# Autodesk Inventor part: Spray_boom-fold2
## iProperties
Created: 2007-04
Part Number: Spray_boom-fold2
Material: Steel, Mild
Document SubType Name: Sheet Metal
Designer: Admin
Density: 1 g/cm^3
Sheet Metal Rule: Default
Author: Admin
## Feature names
1. Bend5
2. Rectangular Pattern2
3. Plate1
4. Plate2
5. Bend1
6. Plate4
7. Bend4
8. Cut2
